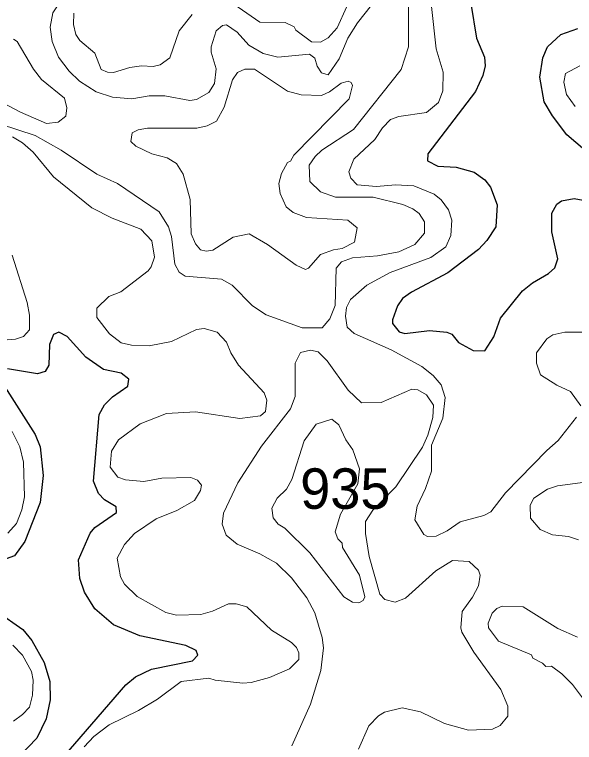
# Model space of a CAD drawing. Extents: x 763.2 to 816.8, y 7896.5 to 7952.7.
# Drawn here: x 780.065 to 782.278, y 7939.255 to 7942.132 of the extents above; entities that cross this region are included whole.
import ezdxf

# ---------------------------------------------------------------- set-up
doc = ezdxf.new("R2010")
doc.units = 0
doc.header["$LTSCALE"] = 0.064
doc.layers.add('1', color=7, linetype='Continuous', lineweight=25)
doc.layers.add('2', color=7, linetype='Continuous', lineweight=13)
doc.layers.add('21', color=7, linetype='Continuous')

msp = doc.modelspace()

# ---------------------------------------------------------------- linework, layer by layer
at = {"layer": '1'}
for points in [[(781.8688, 7942.175), (781.8901, 7942.038), (781.9217, 7941.9634), (781.9249, 7941.9285), (781.9162, 7941.8907), (781.8863, 7941.8274), (781.6983, 7941.5818), (781.6967, 7941.5541), (781.7377, 7941.532), (781.8099, 7941.5285), (781.8815, 7941.509), (781.924, 7941.4783), (781.9454, 7941.4496), (781.9723, 7941.3796), (781.9674, 7941.2923), (781.9319, 7941.2394), (781.8989, 7941.2035)], [(782.3894, 7941.5355), (782.2471, 7941.6567), (782.1911, 7941.731), (782.1586, 7941.7868), (782.1404, 7941.8843), (782.1528, 7941.9604), (782.1718, 7942.0039), (782.2241, 7942.0526), (782.2915, 7942.0769)], [(781.5585, 7940.9247), (781.5591, 7940.9114), (781.5854, 7940.8775), (781.6074, 7940.8711), (781.7047, 7940.8825), (781.774, 7940.8766), (781.7933, 7940.8692), (781.8194, 7940.8356), (781.8773, 7940.8036), (781.9237, 7940.8027), (781.9585, 7940.858), (781.9858, 7940.9319), (782.0729, 7941.0403), (782.1113, 7941.0719), (782.1747, 7941.1078), (782.1996, 7941.1314), (782.2123, 7941.1661), (782.1881, 7941.273), (782.1883, 7941.3466), (782.2078, 7941.3821), (782.2262, 7941.396), (782.2766, 7941.4052), (782.3988, 7941.3825)], [(781.8989, 7941.2035), (781.7777, 7941.1114), (781.6331, 7941.0341), (781.5985, 7941.0093), (781.578, 7940.9805), (781.5585, 7940.9247)], [(780.4171, 7940.7296), (780.3473, 7940.7775), (780.2733, 7940.8595), (780.2404, 7940.8772), (780.2194, 7940.8676), (780.203, 7940.8274), (780.2006, 7940.7458), (780.1868, 7940.7211), (780.1559, 7940.7119), (780.0371, 7940.7312)], [(780.4213, 7940.59), (780.4526, 7940.6213), (780.5129, 7940.6629), (780.5165, 7940.6908), (780.4864, 7940.7143), (780.4171, 7940.7296)], [(780.0175, 7940.6751), (780.147, 7940.4726), (780.1661, 7940.4232), (780.178, 7940.3107), (780.1666, 7940.203), (780.1064, 7940.0494), (780.0653, 7939.9929), (780.0024, 7939.9701)], [(780.2366, 7939.1715), (780.5045, 7939.4831), (780.5425, 7939.5144), (780.6062, 7939.5445), (780.7689, 7939.5777), (780.7889, 7939.6004), (780.7831, 7939.6181), (780.7417, 7939.6384), (780.5602, 7939.6766), (780.4564, 7939.7204), (780.3818, 7939.7832), (780.3418, 7939.8485), (780.3229, 7939.9024), (780.3179, 7939.9761), (780.3645, 7940.0823), (780.3824, 7940.1039), (780.4686, 7940.1636), (780.4665, 7940.186), (780.4203, 7940.2134), (780.3971, 7940.2395), (780.377, 7940.2878), (780.4, 7940.5506), (780.4213, 7940.59)], [(779.9953, 7939.7731), (780.0981, 7939.7014), (780.133, 7939.6584), (780.1828, 7939.5711), (780.2041, 7939.4963), (780.2059, 7939.424), (780.1897, 7939.3479), (780.1532, 7939.2721), (780.0537, 7939.1674)]]:
    msp.add_lwpolyline(points, dxfattribs=at)
at = {"layer": '2'}
for points in [[(780.9314, 7942.173), (781.0339, 7942.1019), (781.1352, 7942.0998), (781.1697, 7942.0828), (781.1769, 7942.0696), (781.2385, 7942.0234), (781.2747, 7942.0221), (781.304, 7942.0397), (781.34, 7942.0799), (781.454, 7942.3332)], [(780.296, 7942.2598), (780.2159, 7942.1382), (780.2061, 7942.0814), (780.2135, 7942.0254), (780.2392, 7941.9635), (780.2804, 7941.9076)], [(780.2804, 7941.9076), (780.3221, 7941.8688), (780.388, 7941.827), (780.4518, 7941.8049), (780.5287, 7941.7981), (780.597, 7941.811), (780.6584, 7941.8112), (780.7575, 7941.7916), (780.7846, 7941.7965), (780.8324, 7941.8234), (780.8551, 7941.8593), (780.8616, 7941.9173), (780.8422, 7941.9831), (780.8423, 7942.0048), (780.8617, 7942.0675), (780.8867, 7942.088), (780.9021, 7942.0906), (780.9453, 7942.0625), (780.9907, 7942.0105), (781.0482, 7941.9785), (781.1057, 7941.9629), (781.2312, 7941.9752), (781.2513, 7941.9597), (781.2611, 7941.9279), (781.2775, 7941.9017), (781.3045, 7941.8939), (781.3477, 7941.9569), (781.3824, 7942.039), (781.4208, 7942.0987), (781.5256, 7942.2334)], [(781.6225, 7942.1901), (781.6225, 7942.0041), (781.5933, 7941.9141), (781.4049, 7941.6774), (781.2796, 7941.5962), (781.2528, 7941.5712), (781.2299, 7941.5363), (781.2319, 7941.4723), (781.274, 7941.4306), (781.334, 7941.4102), (781.4826, 7941.4099), (781.5989, 7941.3807), (781.6396, 7941.3637), (781.664, 7941.3456), (781.6848, 7941.3132), (781.685, 7941.2681), (781.6468, 7941.2225), (781.5837, 7941.1935), (781.4996, 7941.1783), (781.4002, 7941.1698), (781.3566, 7941.1551), (781.3367, 7941.1294), (781.3327, 7940.9824), (781.3107, 7940.9292), (781.2801, 7940.8941), (781.2012, 7940.8943), (781.0599, 7940.9454), (781.0052, 7940.9808), (780.9251, 7941.0621), (780.8836, 7941.086), (780.7391, 7941.0981), (780.716, 7941.1141), (780.6988, 7941.1448), (780.6857, 7941.254), (780.6741, 7941.2934), (780.6369, 7941.352), (780.4721, 7941.4642), (780.3901, 7941.5006), (780.2496, 7941.5962), (780.1467, 7941.6533), (780.0094, 7941.6991)], [(781.713, 7942.1639), (781.7311, 7941.9969), (781.7589, 7941.9041), (781.7572, 7941.8299), (781.741, 7941.784), (781.6936, 7941.7443), (781.5838, 7941.729), (781.5512, 7941.7165), (781.5191, 7941.6846), (781.4883, 7941.6375), (781.4053, 7941.5603), (781.386, 7941.5099), (781.3939, 7941.4854), (781.4187, 7941.4593), (781.4959, 7941.4528), (781.57, 7941.4594), (781.6432, 7941.455), (781.7238, 7941.4219), (781.7506, 7941.4002), (781.78, 7941.3597), (781.7933, 7941.3197), (781.7886, 7941.258), (781.7696, 7941.214), (781.7107, 7941.1715), (781.5496, 7941.1124), (781.4577, 7941.0629), (781.393, 7941.0062), (781.3763, 7940.9739), (781.373, 7940.9401), (781.3794, 7940.8966)], [(780.2995, 7942.1375), (780.298, 7942.093), (780.3077, 7942.0534), (780.3227, 7942.0298), (780.3829, 7941.9791), (780.4074, 7941.9143), (780.4321, 7941.9035), (780.4556, 7941.9032), (780.5214, 7941.9229), (780.5675, 7941.9294), (780.6135, 7941.9262), (780.6402, 7941.933), (780.6788, 7941.9609), (780.716, 7942.0673), (780.7667, 7942.132)], [(779.9133, 7941.838), (780.089, 7941.7464), (780.1919, 7941.7012), (780.2371, 7941.7062), (780.2685, 7941.7296), (780.2724, 7941.7631), (780.263, 7941.8013), (780.1714, 7941.8756), (780.1398, 7941.9154), (780.0756, 7942.0248), (780.0606, 7942.0347)], [(782.28, 7941.7685), (782.246, 7941.8157), (782.2357, 7941.8647), (782.2417, 7941.8989), (782.2989, 7941.9292)], [(780.3702, 7941.3675), (780.2191, 7941.4907), (780.1386, 7941.5876), (780.0963, 7941.625), (780.0567, 7941.6489)], [(780.6054, 7941.135), (780.6184, 7941.1733), (780.6073, 7941.2381), (780.5636, 7941.2837), (780.4504, 7941.3274), (780.3702, 7941.3675)], [(780.0559, 7941.1807), (780.1156, 7940.9937), (780.1239, 7940.9437), (780.1239, 7940.8855), (780.1005, 7940.86), (780.0695, 7940.8483), (780.0186, 7940.8449)], [(780.34, 7939.2372), (780.379, 7939.2791), (780.4393, 7939.3246), (780.5549, 7939.381), (780.6299, 7939.4266), (780.7237, 7939.4953), (780.833, 7939.5087), (780.8576, 7939.5007), (780.9679, 7939.4894), (780.9997, 7939.4918), (781.0729, 7939.5118), (781.1519, 7939.5462), (781.1885, 7939.5834), (781.1887, 7939.6088), (781.1792, 7939.6309), (781.1594, 7939.6496), (781.0806, 7939.6987), (780.9825, 7939.7915), (780.9404, 7939.8025), (780.9103, 7939.8028), (780.8468, 7939.7733), (780.8008, 7939.7602), (780.705, 7939.7576), (780.6629, 7939.7684), (780.5494, 7939.8325), (780.4996, 7939.8804), (780.4835, 7939.9094), (780.4705, 7939.9836), (780.5002, 7940.0379), (780.5396, 7940.0806), (780.6244, 7940.1393), (780.7069, 7940.1716), (780.7765, 7940.2114), (780.8004, 7940.2509), (780.8042, 7940.2723), (780.7882, 7940.2917), (780.7614, 7940.3023), (780.6471, 7940.2991), (780.5766, 7940.2861), (780.5039, 7940.2927), (780.4733, 7940.3033), (780.4431, 7940.343), (780.4479, 7940.4064), (780.4762, 7940.4508), (780.5616, 7940.5148), (780.6655, 7940.5553), (780.7804, 7940.5621), (780.9553, 7940.5359), (781.0374, 7940.5464), (781.0573, 7940.563), (781.0618, 7940.6077), (781.052, 7940.6374), (780.9506, 7940.7462), (780.9193, 7940.795), (780.9028, 7940.8365), (780.8657, 7940.8759), (780.8147, 7940.8906), (780.7845, 7940.8875), (780.685, 7940.8401), (780.5977, 7940.8219), (780.5269, 7940.8248), (780.4863, 7940.8347), (780.4398, 7940.8705), (780.3901, 7940.9342), (780.3908, 7940.9712), (780.4384, 7941.0174), (780.4858, 7941.0359), (780.5929, 7941.1188), (780.6054, 7941.135)], [(781.3794, 7940.8966), (781.4073, 7940.8711), (781.5529, 7940.8073), (781.6745, 7940.7415), (781.719, 7940.7056), (781.7511, 7940.6678)], [(782.3026, 7940.5849), (782.2619, 7940.6425), (782.2077, 7940.6674), (782.1435, 7940.7076), (782.1278, 7940.7539), (782.1272, 7940.7946), (782.1685, 7940.8501), (782.1921, 7940.8656), (782.2397, 7940.8762), (782.3225, 7940.8761)], [(781.1613, 7939.2415), (781.2345, 7939.4062), (781.2758, 7939.539), (781.2856, 7939.6296), (781.2805, 7939.6704), (781.2516, 7939.767), (781.2207, 7939.8262), (781.1602, 7939.9056), (781.1004, 7939.9634), (781.0344, 7940.0006), (780.9454, 7940.0392), (780.9016, 7940.0738), (780.8856, 7940.118), (780.8904, 7940.1611), (780.9473, 7940.281), (781.0412, 7940.4263), (781.1554, 7940.5731), (781.1739, 7940.6225), (781.1741, 7940.7544), (781.1954, 7940.7968), (781.2346, 7940.8053), (781.2643, 7940.7984), (781.3004, 7940.7626), (781.3832, 7940.6472), (781.4362, 7940.5968), (781.5134, 7940.5982), (781.6355, 7940.6507), (781.6591, 7940.6489), (781.6926, 7940.6292), (781.7211, 7940.588), (781.7181, 7940.5389), (781.6983, 7940.4691), (781.6768, 7940.4225), (781.572, 7940.2653), (781.4813, 7940.1726), (781.4524, 7940.128), (781.4517, 7940.0813), (781.4661, 7939.9901), (781.508, 7939.8409), (781.529, 7939.8195), (781.569, 7939.8097), (781.6099, 7939.8247), (781.7296, 7939.9335), (781.7954, 7939.9735), (781.8612, 7939.9705), (781.8982, 7939.9356), (781.905, 7939.9165), (781.8986, 7939.8743), (781.8748, 7939.8289), (781.8333, 7939.772), (781.8283, 7939.7078), (781.833, 7939.6904), (781.8798, 7939.6119), (781.9864, 7939.4646), (782.0149, 7939.3984), (782.0138, 7939.3589), (781.9844, 7939.3219), (781.9536, 7939.3079), (781.8593, 7939.3033), (781.7646, 7939.3294), (781.6695, 7939.3757), (781.5963, 7939.3919), (781.5266, 7939.3751), (781.5031, 7939.3597), (781.4651, 7939.3208), (781.4249, 7939.2287)], [(781.7511, 7940.6678), (781.7671, 7940.6189), (781.7577, 7940.5367), (781.7125, 7940.4293), (781.7127, 7940.3267), (781.6896, 7940.2591), (781.6555, 7940.1891), (781.6475, 7940.1349), (781.6829, 7940.0763), (781.6964, 7940.0692), (781.731, 7940.0709), (781.7749, 7940.0908), (781.8254, 7940.1268), (781.9202, 7940.1525), (781.9478, 7940.1662), (782.0055, 7940.2416), (782.1681, 7940.4093), (782.2135, 7940.4483), (782.2855, 7940.541)], [(780.0559, 7940.4845), (780.0856, 7940.4231), (780.1007, 7940.3626), (780.104, 7940.2259), (780.0935, 7940.1738), (780.0727, 7940.1201), (780.0389, 7940.0828)], [(782.3398, 7940.2858), (782.2103, 7940.2694), (782.1718, 7940.2566), (782.1178, 7940.2206), (782.1026, 7940.1923), (782.1044, 7940.1418), (782.1428, 7940.097), (782.1904, 7940.0759), (782.2536, 7940.0691), (782.2938, 7940.0557)], [(782.2892, 7939.6717), (782.2122, 7939.7054), (782.0745, 7939.791), (781.9921, 7939.7933), (781.9715, 7939.785), (781.9522, 7939.7666), (781.9369, 7939.7271), (781.9374, 7939.7079), (781.9777, 7939.6553), (782.1076, 7939.6014), (782.1136, 7939.5885), (782.1517, 7939.5688), (782.1644, 7939.5553), (782.1865, 7939.5559), (782.2273, 7939.5267), (782.27, 7939.484), (782.3132, 7939.4259)], [(780.058, 7939.6401), (780.0962, 7939.6002), (780.1316, 7939.5356), (780.1383, 7939.501), (780.1366, 7939.4423), (780.1241, 7939.395), (780.0969, 7939.3653), (780.0613, 7939.3393)]]:
    msp.add_lwpolyline(points, dxfattribs=at)
for points in [[(781.1432, 7941.5466), (781.1552, 7941.553), (781.1691, 7941.576), (781.387, 7941.7992), (781.4006, 7941.8517), (781.3949, 7941.8638), (781.3832, 7941.8683), (781.3557, 7941.8608), (781.3103, 7941.826), (781.2781, 7941.8115), (781.1975, 7941.8142), (781.1432, 7941.8294), (781.0131, 7941.9159), (780.9753, 7941.9161), (780.9462, 7941.9032), (780.9267, 7941.8738), (780.894, 7941.7655), (780.8636, 7941.7103), (780.8265, 7941.6926), (780.7854, 7941.6827), (780.5912, 7941.6829), (780.5533, 7941.6767), (780.5298, 7941.6644), (780.5253, 7941.6304), (780.5441, 7941.6118), (780.608, 7941.5819), (780.668, 7941.5651), (780.7049, 7941.5434), (780.7314, 7941.5009), (780.7597, 7941.4012), (780.7628, 7941.2653), (780.7808, 7941.2251), (780.7999, 7941.2017), (780.8227, 7941.1967), (780.8487, 7941.201), (780.9291, 7941.2515), (780.9924, 7941.2654), (781.065, 7941.2236), (781.1776, 7941.1415), (781.2154, 7941.1246), (781.2263, 7941.1294), (781.2748, 7941.1833), (781.326, 7941.2026), (781.3602, 7941.2066), (781.409, 7941.2321), (781.4185, 7941.2895), (781.382, 7941.3196), (781.2193, 7941.3303), (781.1664, 7941.3492), (781.1389, 7941.3715), (781.1148, 7941.4249), (781.1099, 7941.4644), (781.1197, 7941.5038)], [(781.1611, 7940.294), (781.2091, 7940.4465), (781.2567, 7940.5131), (781.3191, 7940.5326), (781.3471, 7940.5098), (781.3749, 7940.4515), (781.4025, 7940.412), (781.4285, 7940.3364), (781.4212, 7940.2773), (781.3532, 7940.1578), (781.3317, 7940.0868), (781.3433, 7940.0597), (781.3593, 7940.0425), (781.3615, 7940.025), (781.4285, 7939.9162), (781.4499, 7939.8303), (781.4427, 7939.8156), (781.4251, 7939.8064), (781.4, 7939.8101), (781.366, 7939.8311), (781.2314, 7940.005), (781.1338, 7940.1023), (781.1068, 7940.118), (781.0873, 7940.1431), (781.0824, 7940.1805), (781.1028, 7940.2208), (781.1393, 7940.2565)]]:
    msp.add_lwpolyline(points, close=True, dxfattribs=at)

# ---------------------------------------------------------------- texts
at = {"layer": '21'}
msp.add_text('935', height=0.16, dxfattribs=at).set_placement((781.1938, 7940.1784))

doc.saveas('drawing.dxf')
